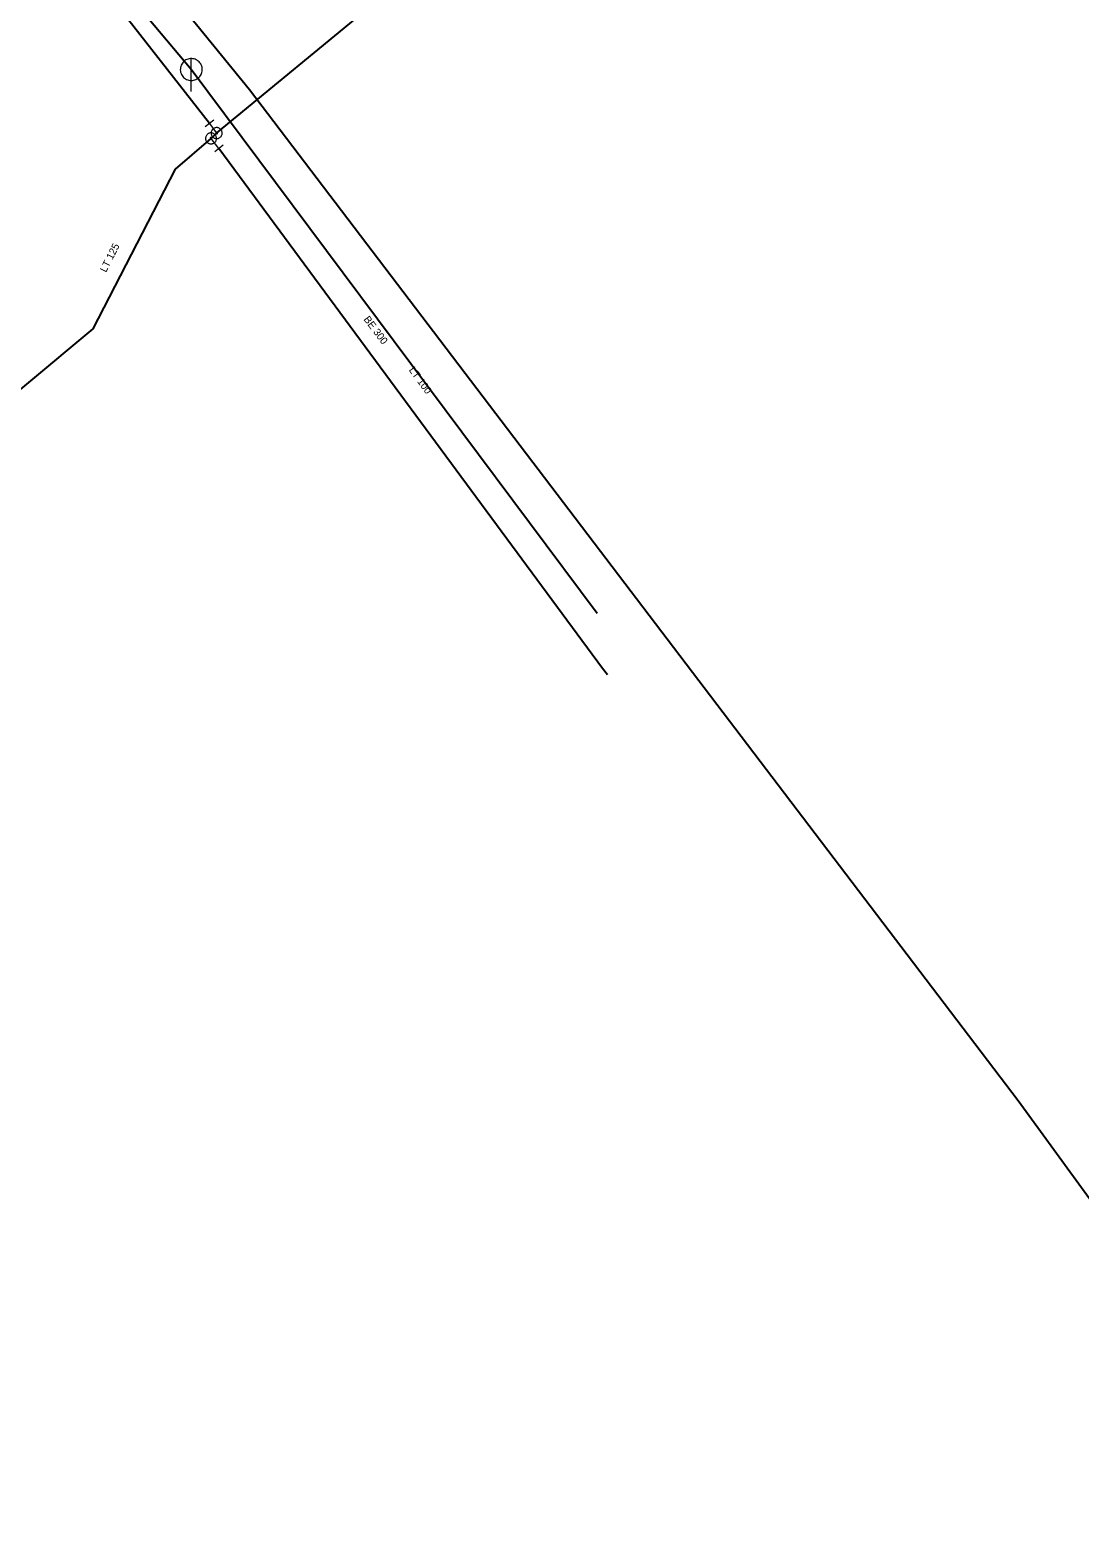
# Model space of a CAD drawing. Extents: x -688296 to -687852, y -973332 to -972816.
# Drawn here: x -688168.6 to -688073, y -973331.6 to -973194.3 of the extents above; entities that cross this region are included whole.
import ezdxf
from ezdxf.enums import TextEntityAlignment as Align

# ---------------------------------------------------------------- set-up
doc = ezdxf.new("R2010")
doc.units = 0
doc.header["$LTSCALE"] = 0.27
for name, color, linetype, lineweight in [('1', 7, 'Continuous', 25), ('14', 7, 'Continuous', 13), ('17', 7, 'Continuous', 25), ('22', 7, 'Continuous', 13), ('34', 7, 'Continuous', 13), ('47', 7, 'Continuous', 13)]:
    doc.layers.add(name, color=color, linetype=linetype, lineweight=lineweight)

msp = doc.modelspace()

# ---------------------------------------------------------------- linework, layer by layer
at = {"layer": '14', "lineweight": 25}
for p, q in [((-688153.927, -973197.923), (-688205.548, -973136.536)), ((-688116.95, -973247.46), (-688153.927, -973197.923))]:
    msp.add_line(p, q, dxfattribs=at)
at = {"layer": '14'}
for p, q in [((-688152.262, -973202.828), (-688151.616, -973203.709)), ((-688151.403, -973205.117), (-688152.126, -973204.191))]:
    msp.add_line(p, q, dxfattribs=at)
at = {"layer": '17'}
for p, q in [((-688152.262, -973202.828), (-688177.473, -973170.632)), ((-688152.126, -973204.191), (-688151.616, -973203.709))]:
    msp.add_line(p, q, dxfattribs=at)
for points in [[(-688123.609, -972815.609), (-688135.91, -972839.761), (-688146.524, -972867.704), (-688149.164, -972878.87), (-688150.368, -972974.473), (-688134.778, -973051.136), (-688125.903, -973068.701), (-688203.651, -973132.27), (-688148.612, -973199.748), (-688078.631, -973291.807), (-688049.631, -973331.642)], [(-688151.616, -973203.709), (-688137.102, -973191.745), (-688123.061, -973180.124), (-688089.804, -973152.646), (-688077.244, -973142.278)], [(-688176.175, -973232.577), (-688174.988, -973231.602), (-688162.877, -973221.524), (-688155.362, -973206.982), (-688152.126, -973204.191)], [(-688116.028, -973253.051), (-688116.482, -973252.462), (-688151.403, -973205.117)]]:
    msp.add_lwpolyline(points, dxfattribs=at)
at = {"layer": '22'}
msp.add_line((-688153.927, -973199.923), (-688153.926, -973196.923), dxfattribs=at)
msp.add_lwpolyline([(-688152.927, -973197.923), (-688152.932, -973197.814), (-688152.95, -973197.706), (-688152.98, -973197.6), (-688153.02, -973197.499), (-688153.072, -973197.402), (-688153.134, -973197.312), (-688153.206, -973197.229), (-688153.286, -973197.155), (-688153.374, -973197.089), (-688153.468, -973197.034), (-688153.568, -973196.989), (-688153.673, -973196.956), (-688153.78, -973196.934), (-688153.889, -973196.924), (-688153.999, -973196.926), (-688154.107, -973196.94), (-688154.214, -973196.965), (-688154.317, -973197.002), (-688154.415, -973197.051), (-688154.507, -973197.109), (-688154.593, -973197.178), (-688154.67, -973197.255), (-688154.739, -973197.341), (-688154.798, -973197.433), (-688154.846, -973197.531), (-688154.883, -973197.634), (-688154.909, -973197.741), (-688154.923, -973197.849), (-688154.926, -973197.959), (-688154.916, -973198.068), (-688154.895, -973198.175), (-688154.861, -973198.279), (-688154.817, -973198.379), (-688154.762, -973198.474), (-688154.696, -973198.562), (-688154.622, -973198.642), (-688154.539, -973198.714), (-688154.449, -973198.776), (-688154.353, -973198.828), (-688154.251, -973198.869), (-688154.146, -973198.899), (-688154.038, -973198.917), (-688153.928, -973198.923), (-688153.819, -973198.917), (-688153.711, -973198.899), (-688153.606, -973198.87), (-688153.504, -973198.829), (-688153.407, -973198.777), (-688153.317, -973198.715), (-688153.234, -973198.644), (-688153.159, -973198.564), (-688153.094, -973198.476), (-688153.038, -973198.382), (-688152.994, -973198.282), (-688152.96, -973198.178), (-688152.938, -973198.07), (-688152.928, -973197.961)], close=True, dxfattribs=at)
at = {"layer": '34'}
for p, q in [((-688151.868, -973202.519), (-688152.655, -973203.135)), ((-688151.009, -973204.808), (-688151.797, -973205.424))]:
    msp.add_line(p, q, dxfattribs=at)
at = {"layer": '47'}
for points in [[(-688151.747, -973203.864), (-688151.783, -973203.827), (-688151.823, -973203.792), (-688151.866, -973203.764), (-688151.912, -973203.738), (-688151.961, -973203.718), (-688152.012, -973203.704), (-688152.063, -973203.695), (-688152.115, -973203.691), (-688152.167, -973203.693), (-688152.219, -973203.699), (-688152.27, -973203.712), (-688152.319, -973203.73), (-688152.366, -973203.752), (-688152.411, -973203.78), (-688152.452, -973203.812), (-688152.489, -973203.848), (-688152.524, -973203.888), (-688152.553, -973203.932), (-688152.578, -973203.977), (-688152.598, -973204.026), (-688152.612, -973204.077), (-688152.621, -973204.128), (-688152.625, -973204.181), (-688152.624, -973204.232), (-688152.617, -973204.284), (-688152.604, -973204.335), (-688152.587, -973204.385), (-688152.564, -973204.431), (-688152.536, -973204.476), (-688152.504, -973204.517), (-688152.468, -973204.554), (-688152.428, -973204.589), (-688152.385, -973204.619), (-688152.339, -973204.643), (-688152.29, -973204.663), (-688152.24, -973204.678), (-688152.188, -973204.687), (-688152.136, -973204.691), (-688152.084, -973204.689), (-688152.032, -973204.682), (-688151.981, -973204.669), (-688151.932, -973204.652), (-688151.885, -973204.629), (-688151.84, -973204.601), (-688151.799, -973204.569), (-688151.762, -973204.533), (-688151.727, -973204.493), (-688151.698, -973204.45), (-688151.673, -973204.404), (-688151.653, -973204.355), (-688151.638, -973204.305), (-688151.63, -973204.254), (-688151.626, -973204.202), (-688151.628, -973204.149), (-688151.634, -973204.097), (-688151.647, -973204.046), (-688151.665, -973203.998), (-688151.687, -973203.95), (-688151.715, -973203.905)], [(-688151.237, -973203.382), (-688151.273, -973203.345), (-688151.313, -973203.31), (-688151.356, -973203.282), (-688151.402, -973203.256), (-688151.451, -973203.236), (-688151.502, -973203.222), (-688151.553, -973203.213), (-688151.605, -973203.209), (-688151.657, -973203.211), (-688151.709, -973203.217), (-688151.76, -973203.23), (-688151.809, -973203.248), (-688151.856, -973203.27), (-688151.901, -973203.298), (-688151.942, -973203.33), (-688151.979, -973203.366), (-688152.014, -973203.406), (-688152.043, -973203.45), (-688152.068, -973203.495), (-688152.088, -973203.544), (-688152.102, -973203.595), (-688152.111, -973203.646), (-688152.115, -973203.699), (-688152.114, -973203.75), (-688152.107, -973203.802), (-688152.094, -973203.853), (-688152.077, -973203.903), (-688152.054, -973203.949), (-688152.026, -973203.994), (-688151.994, -973204.035), (-688151.958, -973204.072), (-688151.918, -973204.107), (-688151.875, -973204.137), (-688151.829, -973204.161), (-688151.78, -973204.181), (-688151.73, -973204.196), (-688151.678, -973204.205), (-688151.626, -973204.209), (-688151.574, -973204.207), (-688151.522, -973204.2), (-688151.471, -973204.187), (-688151.422, -973204.17), (-688151.375, -973204.147), (-688151.33, -973204.119), (-688151.289, -973204.087), (-688151.252, -973204.051), (-688151.217, -973204.011), (-688151.188, -973203.968), (-688151.163, -973203.922), (-688151.143, -973203.873), (-688151.128, -973203.823), (-688151.12, -973203.772), (-688151.116, -973203.72), (-688151.118, -973203.667), (-688151.124, -973203.615), (-688151.137, -973203.564), (-688151.155, -973203.516), (-688151.177, -973203.468), (-688151.205, -973203.423)], [(-688151.553, -973203.655), (-688151.559, -973203.648), (-688151.566, -973203.643), (-688151.573, -973203.639), (-688151.58, -973203.635), (-688151.589, -973203.631), (-688151.597, -973203.629), (-688151.605, -973203.627), (-688151.614, -973203.626), (-688151.622, -973203.627), (-688151.631, -973203.628), (-688151.639, -973203.63), (-688151.648, -973203.633), (-688151.655, -973203.637), (-688151.662, -973203.641), (-688151.669, -973203.646), (-688151.676, -973203.652), (-688151.681, -973203.659), (-688151.685, -973203.666), (-688151.689, -973203.673), (-688151.693, -973203.682), (-688151.695, -973203.69), (-688151.697, -973203.698), (-688151.698, -973203.707), (-688151.698, -973203.716), (-688151.696, -973203.724), (-688151.694, -973203.732), (-688151.691, -973203.741), (-688151.687, -973203.748), (-688151.683, -973203.755), (-688151.678, -973203.762), (-688151.672, -973203.769), (-688151.665, -973203.774), (-688151.658, -973203.778), (-688151.651, -973203.782), (-688151.642, -973203.786), (-688151.635, -973203.789), (-688151.626, -973203.79), (-688151.617, -973203.791), (-688151.608, -973203.791), (-688151.6, -973203.789), (-688151.592, -973203.787), (-688151.583, -973203.784), (-688151.576, -973203.78), (-688151.569, -973203.776), (-688151.562, -973203.771), (-688151.555, -973203.765), (-688151.55, -973203.758), (-688151.546, -973203.751), (-688151.542, -973203.744), (-688151.538, -973203.735), (-688151.535, -973203.728), (-688151.534, -973203.719), (-688151.533, -973203.71), (-688151.534, -973203.702), (-688151.535, -973203.693), (-688151.537, -973203.685), (-688151.54, -973203.676), (-688151.544, -973203.669), (-688151.548, -973203.662)], [(-688152.063, -973204.137), (-688152.069, -973204.13), (-688152.076, -973204.125), (-688152.083, -973204.121), (-688152.09, -973204.117), (-688152.099, -973204.113), (-688152.107, -973204.111), (-688152.115, -973204.109), (-688152.124, -973204.108), (-688152.132, -973204.109), (-688152.141, -973204.11), (-688152.149, -973204.112), (-688152.158, -973204.115), (-688152.165, -973204.119), (-688152.172, -973204.123), (-688152.179, -973204.128), (-688152.186, -973204.134), (-688152.191, -973204.141), (-688152.195, -973204.148), (-688152.199, -973204.155), (-688152.203, -973204.164), (-688152.205, -973204.172), (-688152.207, -973204.18), (-688152.208, -973204.189), (-688152.208, -973204.198), (-688152.206, -973204.206), (-688152.204, -973204.214), (-688152.201, -973204.223), (-688152.197, -973204.23), (-688152.193, -973204.237), (-688152.188, -973204.244), (-688152.182, -973204.251), (-688152.175, -973204.256), (-688152.168, -973204.26), (-688152.161, -973204.264), (-688152.152, -973204.268), (-688152.145, -973204.271), (-688152.136, -973204.272), (-688152.127, -973204.273), (-688152.118, -973204.273), (-688152.11, -973204.271), (-688152.102, -973204.269), (-688152.093, -973204.266), (-688152.086, -973204.262), (-688152.079, -973204.258), (-688152.072, -973204.253), (-688152.065, -973204.247), (-688152.06, -973204.24), (-688152.056, -973204.233), (-688152.052, -973204.226), (-688152.048, -973204.217), (-688152.045, -973204.21), (-688152.044, -973204.201), (-688152.043, -973204.192), (-688152.044, -973204.184), (-688152.045, -973204.175), (-688152.047, -973204.167), (-688152.05, -973204.158), (-688152.054, -973204.151), (-688152.058, -973204.144)]]:
    msp.add_lwpolyline(points, close=True, dxfattribs=at)

# ---------------------------------------------------------------- texts
at = {"layer": '1'}
for s, rotation, p in [('LT 125', 63, (-688161.0654, -973215.2054)), ('LT 125', 63, (-688161.0654, -973215.2054)), ('LT 125', 63, (-688161.0654, -973215.2054)), ('LT 125', 63, (-688161.0654, -973215.2054)), ('LT 125', 63, (-688161.0654, -973215.2054)), ('BE 300', 307, (-688137.3869, -973221.8482)), ('BE 300', 307, (-688137.3869, -973221.8482)), ('BE 300', 307, (-688137.3869, -973221.8482)), ('BE 300', 307, (-688137.3869, -973221.8482)), ('BE 300', 307, (-688137.3869, -973221.8482)), ('LT 100', 306, (-688133.3302, -973226.4146)), ('LT 100', 306, (-688133.3302, -973226.4146)), ('LT 100', 306, (-688133.3302, -973226.4146)), ('LT 100', 306, (-688133.3302, -973226.4146)), ('LT 100', 306, (-688133.3302, -973226.4146))]:
    msp.add_text(s, height=0.6667, rotation=rotation, dxfattribs=at).set_placement(p, align=Align.CENTER)

doc.saveas('drawing.dxf')
